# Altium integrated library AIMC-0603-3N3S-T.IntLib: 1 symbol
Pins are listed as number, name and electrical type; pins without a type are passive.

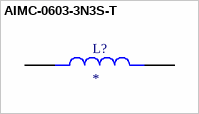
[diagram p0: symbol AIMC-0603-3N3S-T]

## AIMC-0603-3N3S-T
designator L?
IND 3.3nH 0.5A 120mâ„¦; MP: AIMC-0603-3N3S-T; MF: Abracon
footprint INDC1608X95N
pins: 1, 2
